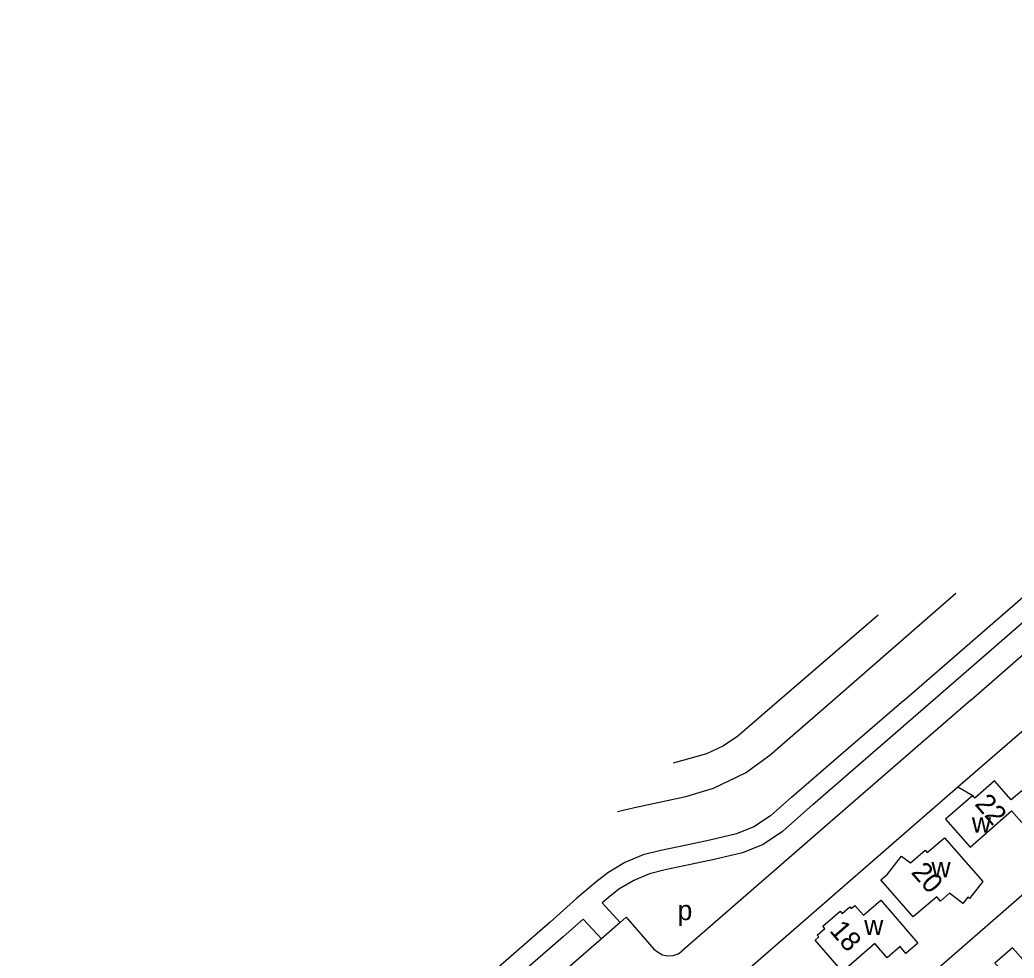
# Model space of a CAD drawing. Extents: x 155854 to 157362, y 383621 to 384685.
# Drawn here: x 156247.8 to 156448.5, y 384447.9 to 384637.3 of the extents above; entities that cross this region are included whole.
import ezdxf

# ---------------------------------------------------------------- set-up
doc = ezdxf.new("R2010")
doc.units = 0
for name, color, linetype in [('BLT_Basislijn', 7, 'Continuous'), ('BLT_Bebouwing', 7, 'Continuous'), ('BLT_Centroide', 7, 'Continuous'), ('BLT_Huisnummer', 7, 'Continuous'), ('BLT_Vlakafsluiter', 7, 'Continuous')]:
    doc.layers.add(name, color=color, linetype=linetype)

msp = doc.modelspace()

# ---------------------------------------------------------------- linework, layer by layer
at = {"layer": 'BLT_Basislijn'}
for p, q in [((156432.17, 384500), (156447.54, 384513.37)), ((156439.76, 384500), (156453.52, 384512.02)), ((156407.9, 384478.9), (156432.15, 384499.98)), ((156439.74, 384499.98), (156411.39, 384475.35)), ((156413.05, 384488.6), (156426.27, 384499.98)), ((156426.27, 384499.98), (156426.29, 384500)), ((156432.15, 384499.98), (156432.17, 384500)), ((156437.14, 384482.49), (156457.27, 384499.98)), ((156439.74, 384499.98), (156439.76, 384500)), ((156403.55, 384480.42), (156413.05, 384488.6)), ((156389.76, 384441.33), (156437.14, 384482.49)), ((156411.39, 384475.35), (156381.46, 384449.34)), ((156406.16, 384422.46), (156452.57, 384462.81)), ((156365.33, 384459.07), (156369, 384455.09)), ((156361.53, 384455.81), (156365.23, 384451.81)), ((156354.83, 384455.2), (156247.82, 384361.74)), ((156357.48, 384452.21), (156258.53, 384366.4))]:
    msp.add_line(p, q, dxfattribs=at)
for points in [[(156426.29, 384500), (156571.71, 384626.22), (156580.21, 384637.32)], [(156447.54, 384513.37), (156473.64, 384536.04)], [(156368.46, 384477.53), (156371.85, 384478.32), (156382.25, 384480.54), (156387.81, 384482.2), (156394.29, 384485.34), (156399.22, 384488.89), (156411.96, 384500), (156436.72, 384521.59)], [(156421.08, 384517.18), (156401.17, 384500), (156392.75, 384492.74), (156389.84, 384490.76), (156386.38, 384489.13), (156379.68, 384487.27)], [(156403.55, 384480.42), (156399.31, 384476.65), (156395.97, 384474.43), (156392.44, 384472.99), (156387.08, 384471.71), (156382.4, 384470.75), (156377.17, 384469.65), (156373.6, 384468.76), (156369.96, 384467.2), (156366.48, 384465.13), (156364.06, 384463.22), (156360.27, 384460.05), (156354.83, 384455.2)], [(156407.9, 384478.9), (156401.76, 384473.48), (156397.86, 384470.87), (156393.67, 384469.17), (156387.94, 384467.8), (156383.21, 384466.83), (156378.07, 384465.75), (156374.88, 384464.96), (156371.77, 384463.62), (156368.75, 384461.83), (156366.58, 384460.12), (156365.33, 384459.07)], [(156361.53, 384455.81), (156357.48, 384452.21)], [(156370.23, 384456.16), (156369, 384455.09)], [(156370.23, 384456.16), (156375.81, 384449.74), (156376.49, 384449.17), (156377.5, 384448.6), (156378.62, 384448.4), (156379.67, 384448.48), (156380.68, 384448.8), (156381.46, 384449.34)], [(156369, 384455.09), (156365.23, 384451.81)], [(156365.23, 384451.81), (156311.98, 384405.55), (156262.39, 384362.48)]]:
    msp.add_lwpolyline(points, dxfattribs=at)
at = {"layer": 'BLT_Bebouwing'}
for p, q in [((156444.56, 384483.7), (156440.6, 384480.24)), ((156447.94, 384479.84), (156444.56, 384483.7)), ((156450.09, 384481.68), (156447.94, 384479.84)), ((156440.14, 384480.76), (156434.65, 384475.95)), ((156440.6, 384480.24), (156440.14, 384480.76)), ((156439.6, 384470.34), (156448.01, 384477.66)), ((156448.01, 384477.66), (156453.76, 384471.05)), ((156434.65, 384475.95), (156439.6, 384470.34)), ((156430.97, 384469.22), (156434.48, 384472.23)), ((156434.48, 384472.23), (156442.17, 384463.37)), ((156427.59, 384467.14), (156430.54, 384469.72)), ((156430.54, 384469.72), (156430.97, 384469.22)), ((156422.93, 384464.85), (156425.79, 384468.53)), ((156425.79, 384468.53), (156427.59, 384467.14)), ((156421.61, 384463.71), (156422.93, 384464.85)), ((156428.1, 384456.24), (156421.61, 384463.71)), ((156418.1, 384456.57), (156421.58, 384459.6)), ((156421.58, 384459.6), (156429.08, 384450.97)), ((156432.91, 384460.28), (156428.1, 384456.24)), ((156433.64, 384459.45), (156432.91, 384460.28)), ((156435.47, 384461.04), (156433.64, 384459.45)), ((156438.16, 384458.92), (156435.47, 384461.04)), ((156409.88, 384454.39), (156413.36, 384457.41)), ((156413.36, 384457.41), (156413.79, 384456.91)), ((156413.79, 384456.91), (156415.33, 384458.25)), ((156415.33, 384458.25), (156415.62, 384457.91)), ((156415.62, 384457.91), (156416.37, 384458.56)), ((156416.37, 384458.56), (156418.1, 384456.57)), ((156408.77, 384452.55), (156410.31, 384453.89)), ((156410.31, 384453.89), (156409.88, 384454.39)), ((156408.32, 384451.57), (156409.06, 384452.22)), ((156413.59, 384445.5), (156408.32, 384451.57)), ((156409.06, 384452.22), (156408.77, 384452.55)), ((156420.4, 384450.84), (156414.62, 384445.82)), ((156422.88, 384447.99), (156420.4, 384450.84)), ((156425.49, 384450.26), (156422.88, 384447.99)), ((156426.68, 384448.88), (156425.49, 384450.26)), ((156429.08, 384450.97), (156426.68, 384448.88))]:
    msp.add_line(p, q, dxfattribs=at)
for points in [[(156442.17, 384463.37), (156439.52, 384459.94), (156439.18, 384460.21), (156438.16, 384458.92)], [(156453.67, 384450.44), (156450.34, 384447.55), (156448.21, 384449.99), (156444.63, 384446.89), (156446.68, 384444.76)]]:
    msp.add_lwpolyline(points, dxfattribs=at)
at = {"layer": 'BLT_Vlakafsluiter'}
msp.add_line((156437.14, 384482.49), (156440.14, 384480.76), dxfattribs=at)

# ---------------------------------------------------------------- texts
at = {"layer": 'BLT_Centroide'}
for s, p in [('w', (156439.98, 384473.25)), ('w', (156431.82, 384464.25)), ('p', (156380.58, 384455.58)), ('w', (156418.24, 384452.56))]:
    msp.add_text(s, height=4, dxfattribs=at).set_placement(p)
at = {"layer": 'BLT_Huisnummer'}
for s, rotation, p in [('22', 310.9832, (156440.4, 384478.95)), ('20', 310.9821, (156427.56, 384465.16)), ('18', 310.9655, (156411.08, 384453.4))]:
    msp.add_text(s, height=4, rotation=rotation, dxfattribs=at).set_placement(p)

doc.saveas('drawing.dxf')
